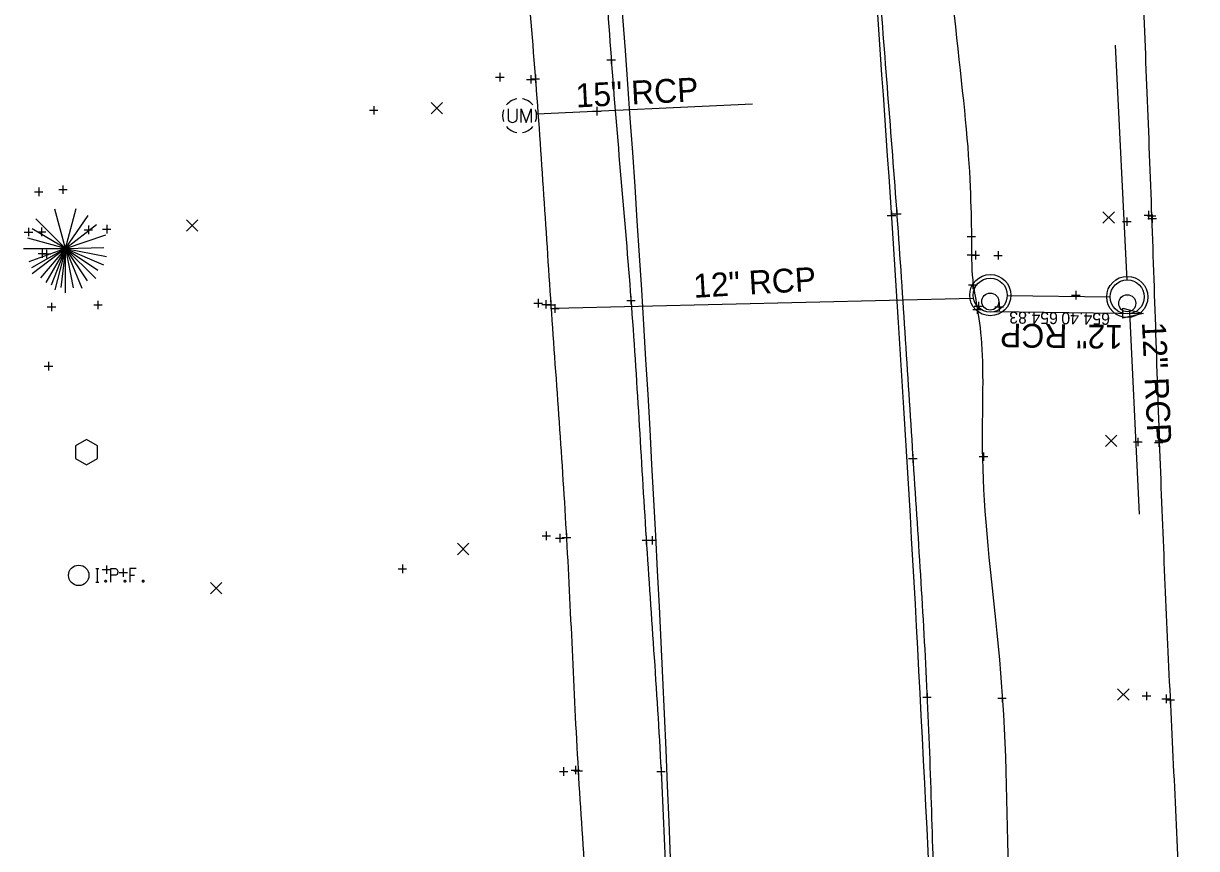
# Model space of a CAD drawing. Extents: x 2188719 to 2189819, y 654569 to 659504.
# Drawn here: x 2189674.3 to 2189812.2, y 657865.9 to 657962.9 of the extents above; entities that cross this region are included whole.
import ezdxf

# ---------------------------------------------------------------- set-up
doc = ezdxf.new("R2010")
doc.units = 0
for name, color, linetype in [('DR_X_Cells', 7, 'Continuous'), ('DR_X_Elev_Flow', 7, 'Continuous'), ('DR_X_Storm_Sewer', 7, 'Continuous'), ('DR_X_Text', 7, 'Continuous'), ('GK_Drainage_Nodes', 7, 'Continuous'), ('PM_X_Edge_Line', 7, 'Continuous'), ('PM_X_Transverse_Line', 7, 'Continuous'), ('PV_X_EOP', 7, 'Continuous'), ('PV_X_Shoulder', 7, 'Continuous'), ('RD_X_Cells', 7, 'Continuous'), ('SC_Scratch1', 7, 'Continuous'), ('SV_X_Mon_Cells_Found', 7, 'Continuous'), ('SV_X_Random_Point', 7, 'Continuous'), ('SV_X_Shot_Marker', 7, 'Continuous'), ('UT_X_Unknown_Cells', 7, 'Continuous'), ('VG_X_Cells', 7, 'Continuous')]:
    doc.layers.add(name, color=color, linetype=linetype)

msp = doc.modelspace()

# ---------------------------------------------------------------- linework, layer by layer
at = {"layer": 'DR_X_Cells'}
for centre, radius in [((2189787.94, 657930.96), 2.42), ((2189787.94, 657930.96), 2), ((2189804.04, 657930.75), 2.42), ((2189804.04, 657930.75), 2), ((2189787.94, 657930.21), 1), ((2189804.04, 657930), 1)]:
    msp.add_circle(centre, radius, dxfattribs=at)
at = {"layer": 'DR_X_Elev_Flow'}
for p, q in [((2189741.21, 657952.59), (2189742.21, 657952.59)), ((2189741.71, 657953.09), (2189741.71, 657952.09)), ((2189741.71, 657952.59), (2189741.71, 657952.59)), ((2189798, 657931.46), (2189798, 657930.46)), ((2189797.5, 657930.96), (2189798.5, 657930.96)), ((2189798, 657930.96), (2189798, 657930.96)), ((2189736.28, 657929.39), (2189737.28, 657929.39)), ((2189736.78, 657929.89), (2189736.78, 657928.89)), ((2189736.78, 657929.39), (2189736.78, 657929.39))]:
    msp.add_line(p, q, dxfattribs=at)
at = {"layer": 'DR_X_Storm_Sewer'}
for p, q in [((2189804.03, 657932.68), (2189802.64, 657960.33)), ((2189734.64, 657952.26), (2189760.01, 657953.46)), ((2189785.94, 657930.56), (2189736.78, 657929.39)), ((2189789.94, 657930.93), (2189802.04, 657930.77)), ((2189804.3, 657929.01), (2189805.45, 657905.21))]:
    msp.add_line(p, q, dxfattribs=at)
at = {"layer": 'DR_X_Text'}
msp.add_line((2189788.42, 657929.05), (2189805.91, 657928.82), dxfattribs=at)
msp.add_lwpolyline([(2189805.91, 657928.82), (2189803.5, 657928.25), (2189803.52, 657929.45)], close=True, dxfattribs=at)
at = {"layer": 'GK_Drainage_Nodes'}
for p, q in [((2189787.94, 657932.96), (2189787.94, 657932.96)), ((2189804.04, 657932.75), (2189804.04, 657932.75)), ((2189787.94, 657930.96), (2189787.94, 657930.96)), ((2189787.94, 657930.96), (2189787.94, 657930.96)), ((2189787.94, 657930.21), (2189787.94, 657930.21)), ((2189804.04, 657930.75), (2189804.04, 657930.75)), ((2189804.04, 657930.75), (2189804.04, 657930.75)), ((2189787.94, 657928.96), (2189787.94, 657928.96)), ((2189804.04, 657930), (2189804.04, 657930)), ((2189804.04, 657928.75), (2189804.04, 657928.75))]:
    msp.add_line(p, q, dxfattribs=at)
for centre in [(2189787.94, 657930.96), (2189804.04, 657930.75)]:
    msp.add_circle(centre, 2, dxfattribs=at)
at = {"layer": 'PM_X_Edge_Line'}
msp.add_open_spline([(2189715.92, 658416.15), (2189719.55, 658398.42), (2189727.31, 658355.37), (2189741.15, 658285.79), (2189752.08, 658199.49), (2189764.73, 658083.92), (2189776.67, 657949.48), (2189785.57, 657773.05), (2189784.87, 657651.45), (2189781.91, 657575.63)], degree=3, dxfattribs=at)
at = {"layer": 'PM_X_Transverse_Line'}
msp.add_open_spline([(2189687.91, 658347.82), (2189695.6, 658312.27), (2189724.53, 658165.17), (2189751.08, 657933.72), (2189754.2, 657738.17), (2189752.07, 657655.83)], degree=3, dxfattribs=at)
at = {"layer": 'PV_X_EOP'}
for points in [[(2189715.65, 658416.09), (2189717.36, 658407.13), (2189721.67, 658389.5), (2189726.25, 658363.76), (2189732.27, 658338.61), (2189735.95, 658313.21), (2189740.83, 658286.81), (2189744.4, 658258.95), (2189748.43, 658232.12), (2189751.61, 658205.72), (2189755.02, 658180.62), (2189757.39, 658155.27), (2189760.52, 658129.99), (2189762.73, 658103.87), (2189765.52, 658076.79), (2189767.84, 658049.53), (2189770.28, 658023.15), (2189773.03, 657997.24), (2189774.6, 657969.67), (2189777.01, 657941.26), (2189778.8, 657911.99), (2189780.69, 657884.09), (2189781.4, 657856.58), (2189782.11, 657829.65), (2189783.53, 657801.33), (2189783.56, 657772.66), (2189783.96, 657743.23), (2189783.95, 657715.3), (2189783.44, 657687.6), (2189783.88, 657660.21), (2189783.01, 657632.25), (2189782.93, 657604.05), (2189782.64, 657585.12), (2189782.5, 657575.65)], [(2189686.87, 658347.88), (2189688.95, 658339.56), (2189693.17, 658321.78), (2189697.87, 658294.9), (2189703.7, 658267.62), (2189707.98, 658241.03), (2189713.11, 658215.13), (2189716.61, 658188.45), (2189721.68, 658160.42), (2189724.61, 658131.33), (2189729.42, 658103.12), (2189732.17, 658074.94), (2189735.91, 658046.42), (2189738.42, 658016.97), (2189741.68, 657987.88), (2189743.15, 657958.86), (2189745.92, 657930.4), (2189747.37, 657902.49), (2189749.54, 657874.27), (2189750.21, 657845.72), (2189752.04, 657816.78), (2189752.93, 657788.08), (2189753.38, 657759.61), (2189754.01, 657732.65), (2189754.13, 657706.9), (2189754.02, 657681.8), (2189752.87, 657664.76), (2189752.08, 657656.03)]]:
    msp.add_open_spline(points, degree=3, dxfattribs=at)
at = {"layer": 'PV_X_Shoulder'}
for points in [[(2189678.17, 658346.51), (2189680.12, 658338.02), (2189683.83, 658320.14), (2189688.68, 658299.1), (2189690.22, 658284.76), (2189692.33, 658279.09), (2189693.11, 658275.51), (2189692.87, 658271.06), (2189696.13, 658259.46), (2189698.82, 658239.7), (2189703.41, 658214.08), (2189707.68, 658187.35), (2189711.85, 658159.43), (2189715.66, 658130.84), (2189719.89, 658102.92), (2189722.84, 658074.64), (2189726.21, 658045.96), (2189729.3, 658016.08), (2189731.79, 657986.57), (2189734.56, 657957.49), (2189736.24, 657929.57), (2189738.31, 657902.49), (2189739.34, 657874.4), (2189741.63, 657845.81), (2189742.72, 657816.8), (2189743.78, 657788), (2189744.99, 657759.47), (2189745.29, 657733.99), (2189744.96, 657716.97), (2189745.15, 657707.52), (2189744.91, 657697.88), (2189745.01, 657680.84), (2189744.6, 657665.71), (2189744.35, 657657.17)], [(2189801.82, 658044.25), (2189802.16, 658038.16), (2189802.98, 658023.46), (2189804.8, 657999.54), (2189805.65, 657970.94), (2189806.89, 657942.16), (2189807.79, 657912.49), (2189808.97, 657884.8), (2189810.47, 657856.11), (2189810.57, 657829.12), (2189810.94, 657800.81), (2189811.25, 657772.16), (2189811.38, 657742.5), (2189812.33, 657713.83), (2189811.88, 657686.44), (2189812.29, 657658.62), (2189811.35, 657630.96), (2189811.25, 657602.53), (2189810.6, 657583.97), (2189810.21, 657574.36)], [(2189779.92, 658011.44), (2189780.4, 658006.73), (2189781.74, 657993.22), (2189782.93, 657968.66), (2189785.63, 657948.14), (2189785.75, 657935.25), (2189785.75, 657932.35), (2189787.48, 657924.59), (2189786.45, 657908.18), (2189789.99, 657883.89), (2189789.91, 657856.04), (2189791.07, 657836.67), (2189791.89, 657825.52), (2189792.21, 657822.44), (2189792.71, 657814.94), (2189792.19, 657798.04), (2189794.52, 657772.31), (2189793.99, 657742.26), (2189794.17, 657721.57), (2189794.66, 657709.58), (2189794.51, 657706.15), (2189795.19, 657698.52), (2189794.06, 657682.99), (2189795.47, 657659.17), (2189794.67, 657631.4), (2189794.75, 657603.18), (2189794.52, 657584.46), (2189794.41, 657574.89)]]:
    msp.add_open_spline(points, degree=3, dxfattribs=at)
at = {"layer": 'RD_X_Cells'}
msp.add_lwpolyline([(2189680.42, 657911.76), (2189681.72, 657911.01), (2189683.02, 657911.76), (2189683.02, 657913.26), (2189681.72, 657914.01), (2189680.42, 657913.26), (2189680.42, 657911.76)], dxfattribs=at)
at = {"layer": 'SV_X_Mon_Cells_Found'}
for points in [[(2189682.82, 657898.83), (2189683.18, 657898.83)], [(2189683, 657897.23), (2189683, 657898.83)], [(2189684.57, 657897.23), (2189684.57, 657898.83), (2189685.1, 657898.83), (2189685.15, 657898.82), (2189685.23, 657898.8), (2189685.26, 657898.77), (2189685.29, 657898.74), (2189685.34, 657898.68), (2189685.37, 657898.62), (2189685.39, 657898.52), (2189685.39, 657898.37), (2189685.38, 657898.32), (2189685.36, 657898.24), (2189685.32, 657898.15), (2189685.27, 657898.11), (2189685.24, 657898.09), (2189685.18, 657898.06), (2189685.1, 657898.05), (2189684.57, 657898.05)], [(2189687.58, 657898.83), (2189686.81, 657898.83), (2189686.81, 657897.23)], [(2189682.82, 657897.23), (2189683.18, 657897.23)], [(2189683.96, 657897.45), (2189684.01, 657897.45), (2189684.05, 657897.42), (2189684.08, 657897.37), (2189684.08, 657897.31), (2189684.05, 657897.26), (2189684.01, 657897.23), (2189683.96, 657897.23), (2189683.93, 657897.26), (2189683.89, 657897.31), (2189683.89, 657897.37), (2189683.93, 657897.42), (2189683.96, 657897.45)], [(2189686.21, 657897.45), (2189686.26, 657897.45), (2189686.3, 657897.42), (2189686.33, 657897.37), (2189686.33, 657897.31), (2189686.3, 657897.26), (2189686.26, 657897.23), (2189686.21, 657897.23), (2189686.18, 657897.26), (2189686.14, 657897.31), (2189686.14, 657897.37), (2189686.18, 657897.42), (2189686.21, 657897.45)], [(2189686.81, 657898.05), (2189687.35, 657898.05)], [(2189688.36, 657897.45), (2189688.41, 657897.45), (2189688.45, 657897.42), (2189688.48, 657897.37), (2189688.48, 657897.31), (2189688.45, 657897.26), (2189688.41, 657897.23), (2189688.36, 657897.23), (2189688.32, 657897.26), (2189688.29, 657897.31), (2189688.29, 657897.37), (2189688.32, 657897.42), (2189688.36, 657897.45)]]:
    msp.add_lwpolyline(points, dxfattribs=at)
msp.add_circle((2189680.81, 657898.03), 1.2, dxfattribs=at)
at = {"layer": 'SV_X_Random_Point'}
for p, q in [((2189722.23, 657952.28), (2189723.56, 657953.62)), ((2189722.23, 657953.62), (2189723.56, 657952.28)), ((2189693.46, 657938.49), (2189694.79, 657939.83)), ((2189693.46, 657939.83), (2189694.79, 657938.49)), ((2189801.18, 657939.43), (2189802.52, 657940.77)), ((2189801.18, 657940.77), (2189802.52, 657939.43)), ((2189801.47, 657913.17), (2189802.8, 657914.51)), ((2189801.47, 657914.51), (2189802.8, 657913.17)), ((2189725.33, 657900.46), (2189726.66, 657901.8)), ((2189725.33, 657901.8), (2189726.66, 657900.46)), ((2189696.3, 657895.86), (2189697.63, 657897.19)), ((2189696.3, 657897.19), (2189697.63, 657895.86)), ((2189802.91, 657883.38), (2189804.25, 657884.71)), ((2189802.91, 657884.71), (2189804.25, 657883.38))]:
    msp.add_line(p, q, dxfattribs=at)
at = {"layer": 'SV_X_Shot_Marker'}
for p, q in [((2189743.39, 657959.12), (2189743.39, 657958.12)), ((2189742.89, 657958.62), (2189743.89, 657958.62)), ((2189743.39, 657958.62), (2189743.39, 657958.62)), ((2189729.81, 657956.57), (2189730.81, 657956.57)), ((2189730.31, 657957.07), (2189730.31, 657956.07)), ((2189730.31, 657956.57), (2189730.31, 657956.57)), ((2189733.43, 657956.32), (2189734.43, 657956.32)), ((2189733.93, 657956.82), (2189733.93, 657955.82)), ((2189733.93, 657956.32), (2189733.93, 657956.32)), ((2189733.98, 657956.4), (2189734.98, 657956.4)), ((2189734.48, 657956.9), (2189734.48, 657955.9)), ((2189734.48, 657956.4), (2189734.48, 657956.4)), ((2189714.98, 657952.69), (2189715.98, 657952.69)), ((2189715.48, 657953.19), (2189715.48, 657952.19)), ((2189715.48, 657952.69), (2189715.48, 657952.69)), ((2189678.96, 657943.86), (2189678.96, 657942.86)), ((2189675.61, 657943.1), (2189676.61, 657943.1)), ((2189676.11, 657943.6), (2189676.11, 657942.6)), ((2189676.11, 657943.1), (2189676.11, 657943.1)), ((2189678.46, 657943.36), (2189679.46, 657943.36)), ((2189678.96, 657943.36), (2189678.96, 657943.36)), ((2189775.84, 657940.31), (2189776.84, 657940.31)), ((2189776.34, 657940.81), (2189776.34, 657939.81)), ((2189776.34, 657940.31), (2189776.34, 657940.31)), ((2189776.45, 657940.5), (2189777.45, 657940.5)), ((2189776.95, 657941), (2189776.95, 657940)), ((2189776.95, 657940.5), (2189776.95, 657940.5)), ((2189803.99, 657940.1), (2189803.99, 657939.1)), ((2189806.04, 657940.36), (2189807.04, 657940.36)), ((2189806.4, 657940.27), (2189807.4, 657940.27)), ((2189806.46, 657939.95), (2189807.46, 657939.95)), ((2189806.54, 657940.86), (2189806.54, 657939.86)), ((2189806.54, 657940.36), (2189806.54, 657940.36)), ((2189806.9, 657940.77), (2189806.9, 657939.77)), ((2189806.9, 657940.27), (2189806.9, 657940.27)), ((2189806.96, 657940.45), (2189806.96, 657939.45)), ((2189806.96, 657939.95), (2189806.96, 657939.95)), ((2189674.4, 657938.38), (2189675.4, 657938.38)), ((2189674.9, 657938.88), (2189674.9, 657937.88)), ((2189674.9, 657938.38), (2189674.9, 657938.38)), ((2189675.95, 657938.41), (2189676.95, 657938.41)), ((2189676.45, 657938.91), (2189676.45, 657937.91)), ((2189676.45, 657938.41), (2189676.45, 657938.41)), ((2189681.45, 657938.63), (2189682.45, 657938.63)), ((2189681.45, 657938.63), (2189682.45, 657938.63)), ((2189681.95, 657939.13), (2189681.95, 657938.13)), ((2189681.95, 657939.13), (2189681.95, 657938.13)), ((2189681.95, 657938.63), (2189681.95, 657938.63)), ((2189681.95, 657938.63), (2189681.95, 657938.63)), ((2189683.6, 657938.71), (2189684.6, 657938.71)), ((2189684.1, 657939.21), (2189684.1, 657938.21)), ((2189684.1, 657938.71), (2189684.1, 657938.71)), ((2189785.72, 657938.35), (2189785.72, 657937.35)), ((2189803.49, 657939.6), (2189804.49, 657939.6)), ((2189803.99, 657939.6), (2189803.99, 657939.6)), ((2189785.22, 657937.85), (2189786.22, 657937.85)), ((2189785.72, 657937.85), (2189785.72, 657937.85)), ((2189676.03, 657935.85), (2189677.03, 657935.85)), ((2189676.52, 657935.8), (2189677.52, 657935.8)), ((2189676.53, 657936.35), (2189676.53, 657935.35)), ((2189676.53, 657935.85), (2189676.53, 657935.85)), ((2189677.02, 657936.3), (2189677.02, 657935.3)), ((2189677.02, 657935.8), (2189677.02, 657935.8)), ((2189785.24, 657935.71), (2189786.24, 657935.71)), ((2189785.69, 657935.65), (2189786.69, 657935.65)), ((2189785.74, 657936.21), (2189785.74, 657935.21)), ((2189785.74, 657935.71), (2189785.74, 657935.71)), ((2189786.19, 657936.15), (2189786.19, 657935.15)), ((2189786.19, 657935.65), (2189786.19, 657935.65)), ((2189788.35, 657935.64), (2189789.35, 657935.64)), ((2189788.85, 657936.14), (2189788.85, 657935.14)), ((2189788.85, 657935.64), (2189788.85, 657935.64)), ((2189785.39, 657932.17), (2189786.39, 657932.17)), ((2189785.89, 657932.67), (2189785.89, 657931.67)), ((2189785.89, 657932.17), (2189785.89, 657932.17)), ((2189683.07, 657930.31), (2189683.07, 657929.31)), ((2189683.07, 657930.31), (2189683.07, 657929.31)), ((2189734.81, 657930.52), (2189734.81, 657929.52)), ((2189735.72, 657930.38), (2189735.72, 657929.38)), ((2189736.3, 657930.34), (2189736.3, 657929.34)), ((2189745.21, 657930.35), (2189746.21, 657930.35)), ((2189745.71, 657930.85), (2189745.71, 657929.85)), ((2189745.71, 657930.35), (2189745.71, 657930.35)), ((2189786.54, 657930.18), (2189786.54, 657929.18)), ((2189788.99, 657930.1), (2189788.99, 657929.1)), ((2189677.11, 657929.57), (2189678.11, 657929.57)), ((2189677.61, 657930.07), (2189677.61, 657929.07)), ((2189677.61, 657929.57), (2189677.61, 657929.57)), ((2189682.57, 657929.81), (2189683.57, 657929.81)), ((2189682.57, 657929.81), (2189683.57, 657929.81)), ((2189683.07, 657929.81), (2189683.07, 657929.81)), ((2189683.07, 657929.81), (2189683.07, 657929.81)), ((2189734.31, 657930.02), (2189735.31, 657930.02)), ((2189734.81, 657930.02), (2189734.81, 657930.02)), ((2189735.22, 657929.88), (2189736.22, 657929.88)), ((2189735.72, 657929.88), (2189735.72, 657929.88)), ((2189735.8, 657929.84), (2189736.8, 657929.84)), ((2189736.3, 657929.84), (2189736.3, 657929.84)), ((2189785.89, 657929.26), (2189786.89, 657929.26)), ((2189786.04, 657929.68), (2189787.04, 657929.68)), ((2189786.39, 657929.76), (2189786.39, 657928.76)), ((2189786.39, 657929.26), (2189786.39, 657929.26)), ((2189786.54, 657929.68), (2189786.54, 657929.68)), ((2189788.49, 657929.6), (2189789.49, 657929.6)), ((2189788.99, 657929.6), (2189788.99, 657929.6)), ((2189676.75, 657922.62), (2189677.75, 657922.62)), ((2189677.25, 657923.12), (2189677.25, 657922.12)), ((2189677.25, 657922.62), (2189677.25, 657922.62)), ((2189804.78, 657913.71), (2189805.78, 657913.71)), ((2189805.28, 657914.21), (2189805.28, 657913.21)), ((2189805.28, 657913.71), (2189805.28, 657913.71)), ((2189807.23, 657913.63), (2189808.23, 657913.63)), ((2189807.3, 657913.83), (2189808.3, 657913.83)), ((2189807.73, 657914.13), (2189807.73, 657913.13)), ((2189807.73, 657913.63), (2189807.73, 657913.63)), ((2189807.8, 657914.33), (2189807.8, 657913.33)), ((2189807.8, 657913.83), (2189807.8, 657913.83)), ((2189778.84, 657912.26), (2189778.84, 657911.26)), ((2189787.14, 657912.48), (2189787.14, 657911.48)), ((2189778.34, 657911.76), (2189779.34, 657911.76)), ((2189778.84, 657911.76), (2189778.84, 657911.76)), ((2189786.64, 657911.98), (2189787.64, 657911.98)), ((2189787.14, 657911.98), (2189787.14, 657911.98)), ((2189735.26, 657902.67), (2189736.26, 657902.67)), ((2189735.76, 657903.17), (2189735.76, 657902.17)), ((2189735.76, 657902.67), (2189735.76, 657902.67)), ((2189737.36, 657902.9), (2189737.36, 657901.9)), ((2189738.13, 657902.99), (2189738.13, 657901.99)), ((2189747.51, 657902.66), (2189747.51, 657901.66)), ((2189748.19, 657902.65), (2189748.19, 657901.65)), ((2189736.86, 657902.4), (2189737.86, 657902.4)), ((2189737.36, 657902.4), (2189737.36, 657902.4)), ((2189737.63, 657902.49), (2189738.63, 657902.49)), ((2189738.13, 657902.49), (2189738.13, 657902.49)), ((2189747.01, 657902.16), (2189748.01, 657902.16)), ((2189747.51, 657902.16), (2189747.51, 657902.16)), ((2189747.69, 657902.15), (2189748.69, 657902.15)), ((2189748.19, 657902.15), (2189748.19, 657902.15)), ((2189683.58, 657898.7), (2189684.58, 657898.7)), ((2189683.58, 657898.7), (2189684.58, 657898.7)), ((2189683.58, 657898.7), (2189684.58, 657898.7)), ((2189684.08, 657899.2), (2189684.08, 657898.2)), ((2189684.08, 657899.2), (2189684.08, 657898.2)), ((2189684.08, 657899.2), (2189684.08, 657898.2)), ((2189684.08, 657898.7), (2189684.08, 657898.7)), ((2189684.08, 657898.7), (2189684.08, 657898.7)), ((2189684.08, 657898.7), (2189684.08, 657898.7)), ((2189686.05, 657898.85), (2189686.05, 657897.85)), ((2189718.35, 657898.79), (2189719.35, 657898.79)), ((2189718.85, 657899.29), (2189718.85, 657898.29)), ((2189718.85, 657898.79), (2189718.85, 657898.79)), ((2189685.55, 657898.35), (2189686.55, 657898.35)), ((2189686.05, 657898.35), (2189686.05, 657898.35)), ((2189780.01, 657883.7), (2189781.01, 657883.7)), ((2189780.51, 657884.2), (2189780.51, 657883.2)), ((2189780.51, 657883.7), (2189780.51, 657883.7)), ((2189788.82, 657883.61), (2189789.82, 657883.61)), ((2189789.32, 657884.11), (2189789.32, 657883.11)), ((2189789.32, 657883.61), (2189789.32, 657883.61)), ((2189805.79, 657883.86), (2189806.79, 657883.86)), ((2189806.29, 657884.36), (2189806.29, 657883.36)), ((2189806.29, 657883.86), (2189806.29, 657883.86)), ((2189808.1, 657883.52), (2189809.1, 657883.52)), ((2189808.58, 657883.39), (2189809.58, 657883.39)), ((2189808.6, 657884.02), (2189808.6, 657883.02)), ((2189808.6, 657883.52), (2189808.6, 657883.52)), ((2189809.08, 657883.89), (2189809.08, 657882.89)), ((2189809.08, 657883.39), (2189809.08, 657883.39)), ((2189737.3, 657874.98), (2189738.3, 657874.98)), ((2189737.8, 657875.48), (2189737.8, 657874.48)), ((2189737.8, 657874.98), (2189737.8, 657874.98)), ((2189738.69, 657875.15), (2189739.69, 657875.15)), ((2189739, 657875.07), (2189740, 657875.07)), ((2189739.19, 657875.65), (2189739.19, 657874.65)), ((2189739.19, 657875.15), (2189739.19, 657875.15)), ((2189739.5, 657875.57), (2189739.5, 657874.57)), ((2189739.5, 657875.07), (2189739.5, 657875.07)), ((2189748.75, 657874.99), (2189749.75, 657874.99)), ((2189749.25, 657875.49), (2189749.25, 657874.49)), ((2189749.25, 657874.99), (2189749.25, 657874.99))]:
    msp.add_line(p, q, dxfattribs=at)
at = {"layer": 'UT_X_Unknown_Cells'}
for p, q in [((2189731.28, 657952.87), (2189731.28, 657951.59)), ((2189732.29, 657952.87), (2189732.29, 657951.59)), ((2189732.63, 657952.05), (2189732.63, 657952.05))]:
    msp.add_line(p, q, dxfattribs=at)
msp.add_lwpolyline([(2189732.81, 657951.27), (2189732.81, 657952.87), (2189733.41, 657951.27), (2189734, 657952.87), (2189734, 657951.27)], dxfattribs=at)
for centre, radius, start, end in [((2189732.63, 657952.05), 2, 100.0806, 140.0721), ((2189732.63, 657952.05), 2, 40.0577, 80.1061), ((2189732.63, 657952.05), 2, 160.0169, 200.0392), ((2189732.63, 657952.05), 2, 340.0169, 20.0392), ((2189732.63, 657952.05), 2, 220.0577, 260.0473), ((2189731.79, 657951.82), 0.557, 205.1924, 334.8076), ((2189732.63, 657952.05), 2, 280.0114, 320.0264)]:
    msp.add_arc(centre, radius, start, end, dxfattribs=at)
at = {"layer": 'VG_X_Cells'}
for p, q in [((2189679.25, 657936.46), (2189680.51, 657941.15)), ((2189679.25, 657936.46), (2189675.76, 657939.94)), ((2189679.25, 657936.46), (2189678.02, 657941.07)), ((2189679.25, 657936.46), (2189681.91, 657940.34)), ((2189679.25, 657936.46), (2189675.35, 657938.75)), ((2189679.25, 657936.46), (2189682.91, 657939.26)), ((2189679.25, 657936.46), (2189674.84, 657937.64)), ((2189679.25, 657936.46), (2189683.99, 657938.06)), ((2189674.32, 657936.46), (2189679.25, 657936.46)), ((2189679.25, 657936.46), (2189674.96, 657934.89)), ((2189679.25, 657936.46), (2189675.27, 657934.17)), ((2189679.25, 657936.46), (2189675.35, 657933.46)), ((2189679.25, 657936.46), (2189676.31, 657932.99)), ((2189679.25, 657936.46), (2189676.93, 657932.44)), ((2189679.25, 657936.46), (2189677.59, 657932.12)), ((2189679.25, 657936.46), (2189677.99, 657931.6)), ((2189679.25, 657936.46), (2189678.71, 657931.86)), ((2189679.25, 657936.46), (2189683.76, 657936.55)), ((2189679.25, 657931.22), (2189679.25, 657936.46)), ((2189679.25, 657936.46), (2189680.17, 657931.82)), ((2189679.25, 657936.46), (2189681.19, 657931.79)), ((2189679.25, 657936.46), (2189681.79, 657932.66)), ((2189679.25, 657936.46), (2189682.84, 657932.93)), ((2189679.25, 657936.46), (2189683.07, 657933.9)), ((2189679.25, 657936.46), (2189683.72, 657934.51)), ((2189679.25, 657936.46), (2189684.08, 657935.5))]:
    msp.add_line(p, q, dxfattribs=at)

# ---------------------------------------------------------------- texts
at = {"layer": 'DR_X_Text'}
for s, rotation, p in [('15" RCP', 2.9998, (2189739.28, 657953.01)), ('12" RCP', 3.3897, (2189753.12, 657930.64)), ('12" RCP', 179.2454, (2189803.55, 657927.45)), ('12" RCP', 272.7681, (2189805.76, 657927.76))]:
    msp.add_text(s, height=2.8, rotation=rotation, dxfattribs=at).set_placement(p)
at = {"layer": 'SC_Scratch1'}
for s, p in [('654.83', (2189795.9, 657928.95)), ('654.40', (2189802.02, 657928.87))]:
    msp.add_text(s, height=1.4, rotation=179.2454, dxfattribs=at).set_placement(p)

doc.saveas('drawing.dxf')
